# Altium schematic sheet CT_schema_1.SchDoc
size 544 x 331 mm
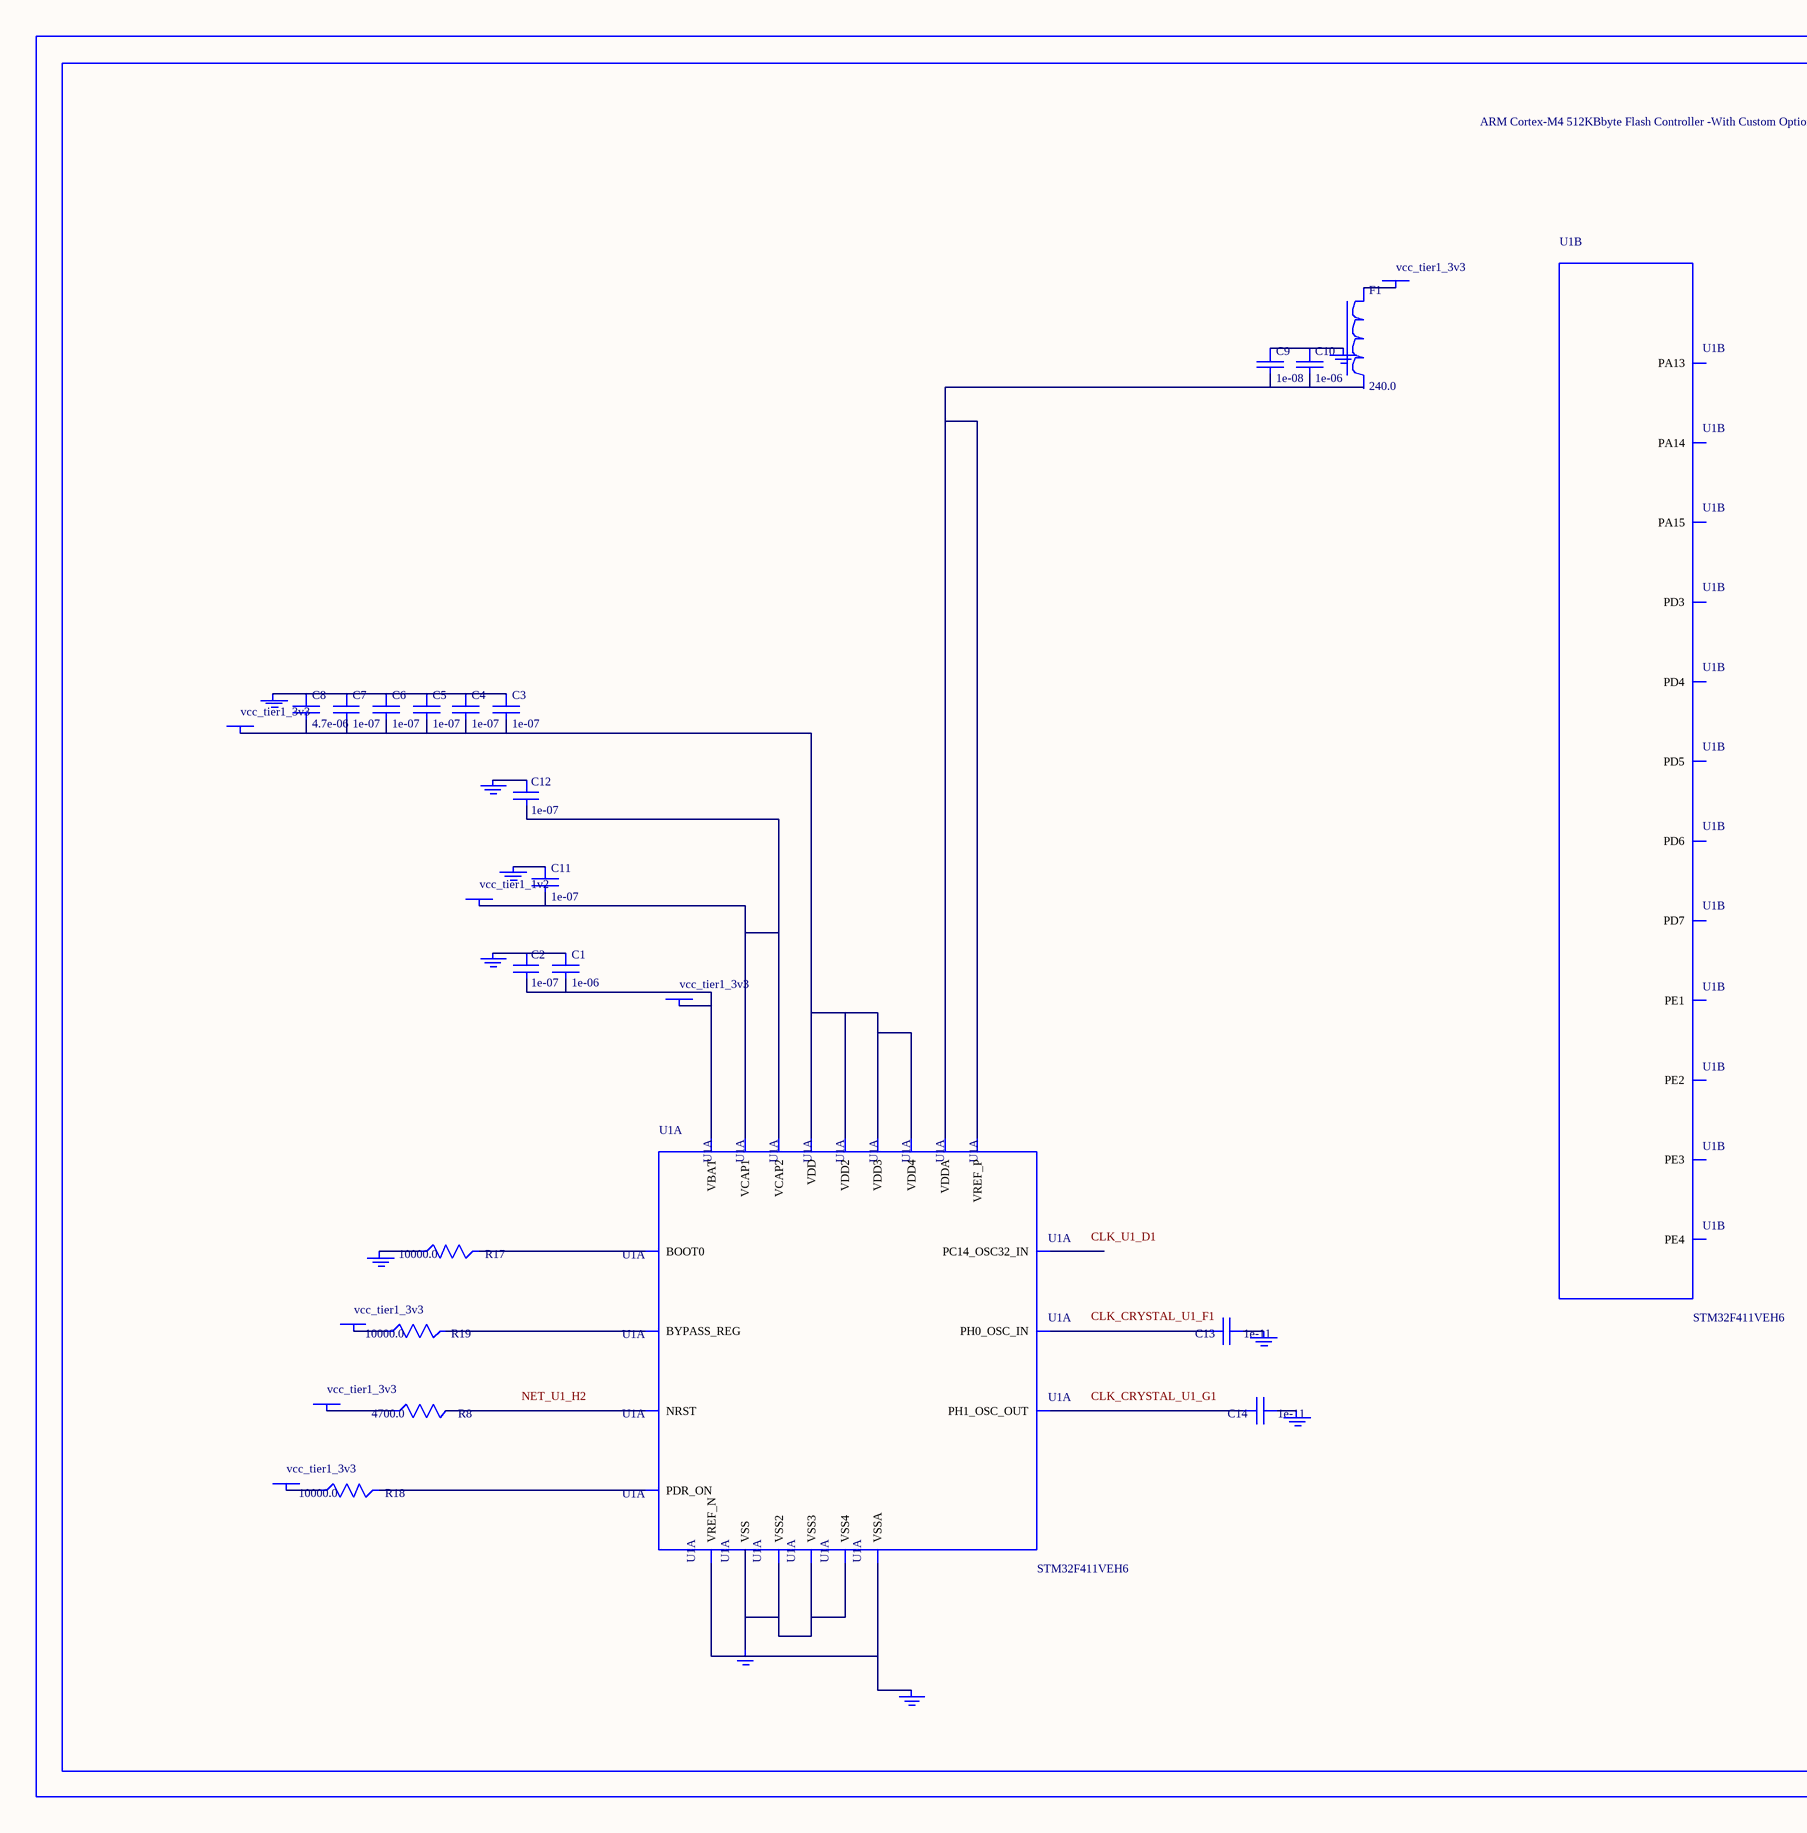
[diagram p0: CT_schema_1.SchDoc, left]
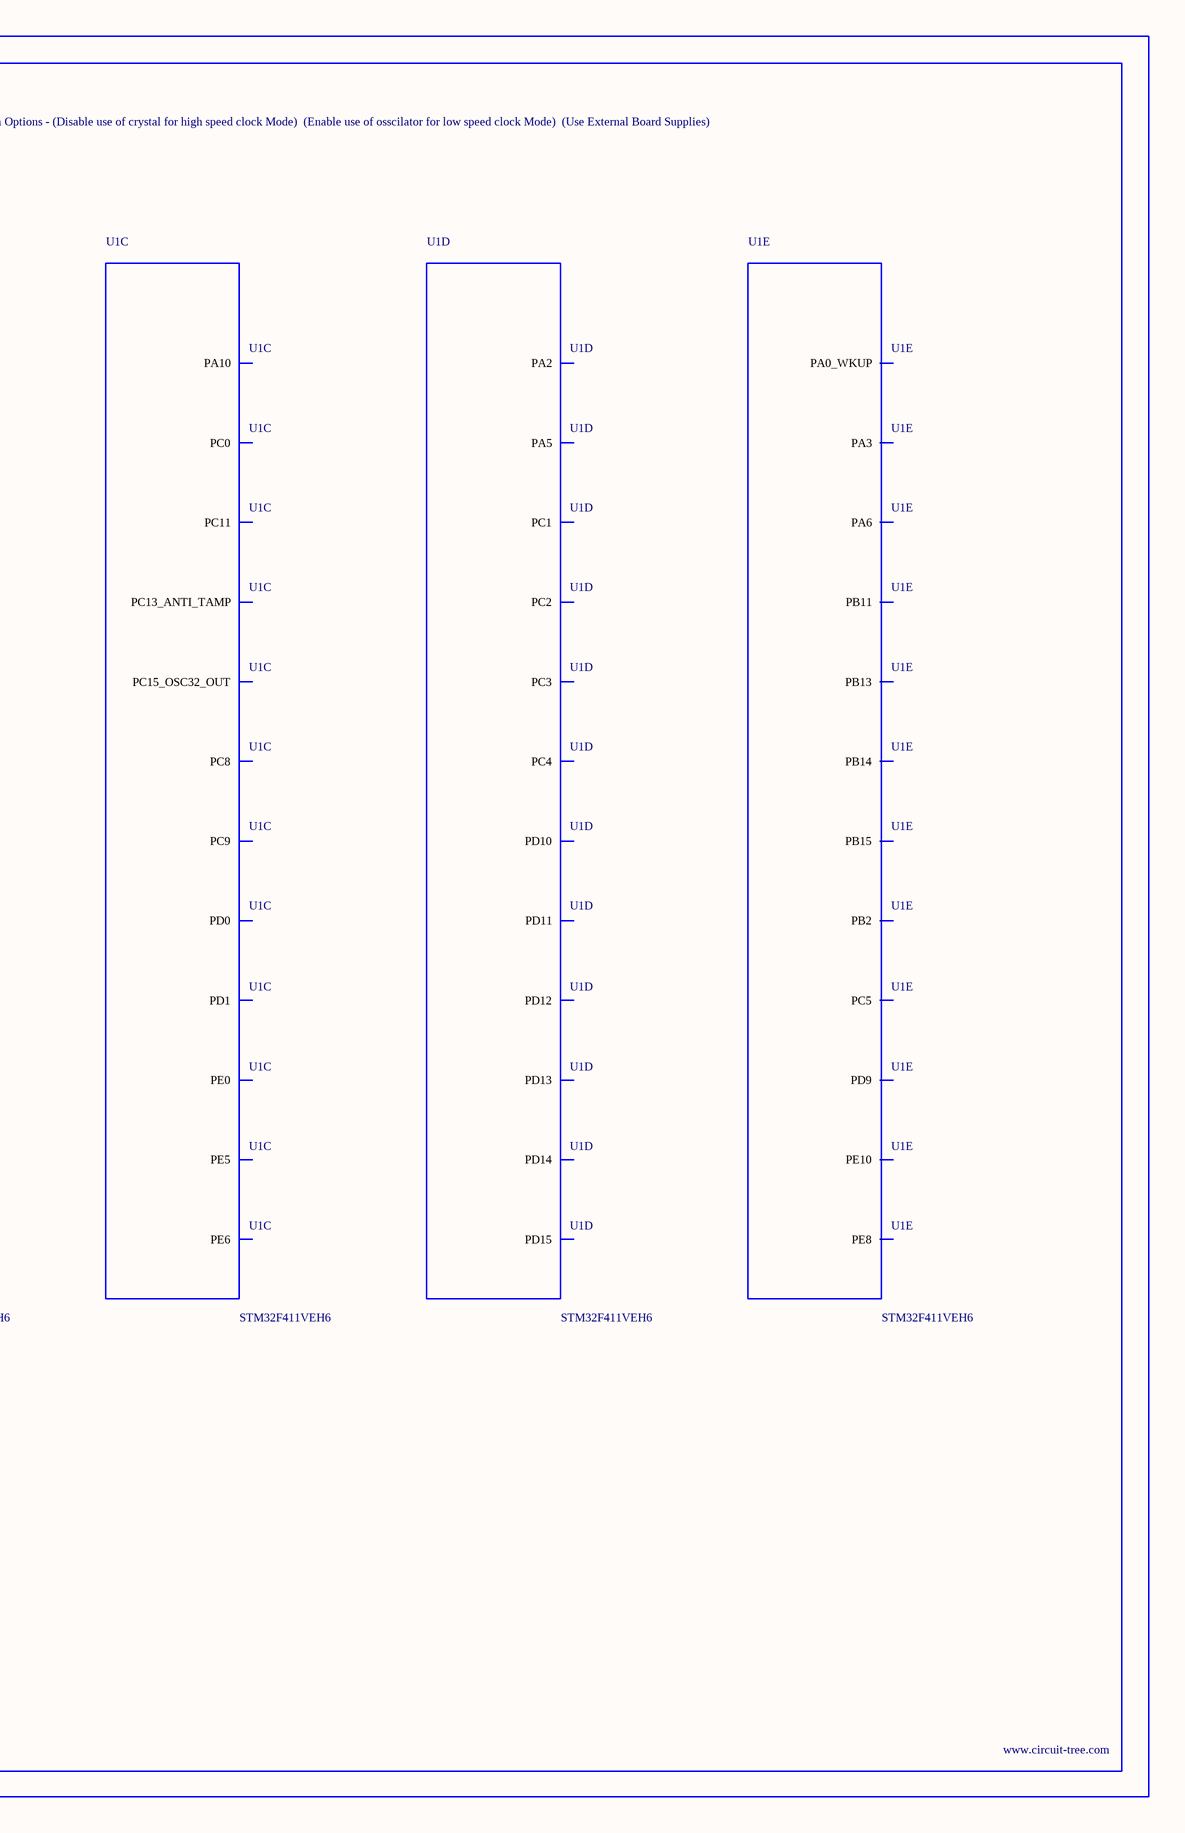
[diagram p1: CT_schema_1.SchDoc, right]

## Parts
BORDER0  (no value)
C1  1e-06  [C0603]
C2  1e-07  [C0603]
C3  1e-07  [C0603]
C4  1e-07  [C0603]
C5  1e-07  [C0603]
C6  1e-07  [C0603]
C7  1e-07  [C0603]
C8  4.7e-06  [C0603]
C9  1e-08  [C0603]
C10  1e-06  [C0603]
C11  1e-07  [C0402]
C12  1e-07  [C0402]
C13  1e-11  [C0402]
C14  1e-11  [C0402]
F1  240.0  [L0603]
GND_INSTANCE_0_0  (no value)
GND_INSTANCE_0_1  (no value)
GND_INSTANCE_0_2  (no value)
GND_INSTANCE_0_3  (no value)
GND_INSTANCE_0_4  (no value)
GND_INSTANCE_0_5  (no value)
GND_INSTANCE_0_6  (no value)
GND_INSTANCE_0_7  (no value)
GND_INSTANCE_0_8  (no value)
GND_INSTANCE_0_9  (no value)
POWER_INSTANCE_0_0  vcc_tier1_3v3
POWER_INSTANCE_0_1  vcc_tier1_3v3
POWER_INSTANCE_0_2  vcc_tier1_3v3
POWER_INSTANCE_0_3  vcc_tier1_3v3
POWER_INSTANCE_0_4  vcc_tier1_3v3
POWER_INSTANCE_0_5  vcc_tier1_1v2
POWER_INSTANCE_0_6  vcc_tier1_3v3
R8  4700.0  [R0603]
R17  10000.0  [R0603]
R18  10000.0  [R0603]
R19  10000.0  [R0603]
U1  STM32F411VEH6  [UFBGA100]  (parts A,B,C,D,E of 8)

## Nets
NetC1_1: C1.1 C2.1 GND_INSTANCE_0_0.0(GND)
NetC1_2: C1.2 C2.2 POWER_INSTANCE_0_0.0(PWR) U1.E2(VBAT)
NetC3_1: C3.1 C4.1 C5.1 C6.1 C7.1 C8.1 GND_INSTANCE_0_2.0(GND)
NetC3_2: C3.2 C4.2 C5.2 C6.2 C7.2 C8.2 POWER_INSTANCE_0_2.0(PWR) U1.C4(VDD) U1.G2(VDD4) U1.G11(VDD2) U1.G12(VDD3)
NetC9_1: C9.1 C10.1 GND_INSTANCE_0_1.0(GND)
NetC9_2: C9.2 C10.2 U1.L1(VREF_P) U1.M1(VDDA)
NetC11_1: C11.1 GND_INSTANCE_0_4.0(GND)
NetC11_2: C11.2 C12.2 POWER_INSTANCE_0_5.0(PWR) U1.C11(VCAP2) U1.L11(VCAP1)
NetC12_1: C12.1 GND_INSTANCE_0_5.0(GND)
NetC13_1: C13.1 GND_INSTANCE_0_6.0(GND)
NetC13_2: C13.2 U1.F1(PH0_OSC_IN)
NetC14_1: C14.1 GND_INSTANCE_0_7.0(GND)
NetC14_2: C14.2 U1.G1(PH1_OSC_OUT)
NetF1_1: F1.1 POWER_INSTANCE_0_1.0(PWR)
NetGND_INSTANCE_0_3_0: GND_INSTANCE_0_3.0(GND) R17.1
NetGND_INSTANCE_0_8_0: GND_INSTANCE_0_8.0(GND) U1.J1(VSSA) U1.K1(VREF_N)
NetGND_INSTANCE_0_9_0: GND_INSTANCE_0_9.0(GND) U1.D3(VSS) U1.F2(VSS4) U1.F11(VSS2) U1.F12(VSS3)
NetPOWER_INSTANCE_0_3_0: POWER_INSTANCE_0_3.0(PWR) R18.1
NetPOWER_INSTANCE_0_4_0: POWER_INSTANCE_0_4.0(PWR) R19.1
NetPOWER_INSTANCE_0_6_0: POWER_INSTANCE_0_6.0(PWR) R8.1
NetR8_2: R8.2 U1.H2(NRST)
NetR17_2: R17.2 U1.A4(BOOT0)
NetR18_2: R18.2 U1.H3(PDR_ON)
NetR19_2: R19.2 U1.E3(BYPASS_REG)

Not connected (* = marked no-connect by the designer): F1 2; U1 A1(PE3) A2(PE1) A5(PD7) A6(PD5) A9(PA15) A10(PA14) A11(PA13) B1(PE4) B2(PE2) B6(PD6) B7(PD4) B8(PD3) B9(PD1) C1(PC13_ANTI_TAMP) C2(PE5) C3(PE0) C9(PD0) C10(PC11) C12(PA10) D1(PC14_OSC32_IN) D2(PE6) D12(PC9) E1(PC15_OSC32_OUT) E10(PC8) H1(PC0) H10(PD15) H11(PD14) H12(PD13) J2(PC1) J3(PC2) J10(PD12) J11(PD11) J12(PD10) K2(PC3) K3(PA2) K4(PA5) K5(PC4) K8(PD9) K9(PB11) K10(PB15) K11(PB14) K12(PB13) L2(PA0_WKUP) L3(PA3) L4(PA6) L5(PC5) L6(PB2) L7(PE8) L8(PE10)

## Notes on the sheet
- Labels drawn without touching a wire or pin: CLK_CRYSTAL_U1_F1, CLK_CRYSTAL_U1_G1, CLK_U1_D1, NET_U1_H2

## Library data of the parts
BORDER0 = BORDER_PAGE0
C1 C10 = C0603C105K3RACTU
C2-C7 = 06035C104K4Z2A
C8 = GRM188R6YA475KE15D
C9 = 06035C103K4Z2A
C11 C12 = C0402C104K3RACTU
C13 C14 = C0402C100K3GACTU
F1 = Z0603C241ASMST
GND_INSTANCE_0_0-GND_INSTANCE_0_9 = GND
POWER_INSTANCE_0_0-POWER_INSTANCE_0_6 = PWR
R8 = RC0603JR-074K7L
R17-R19 = RC0603JR-0710KL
